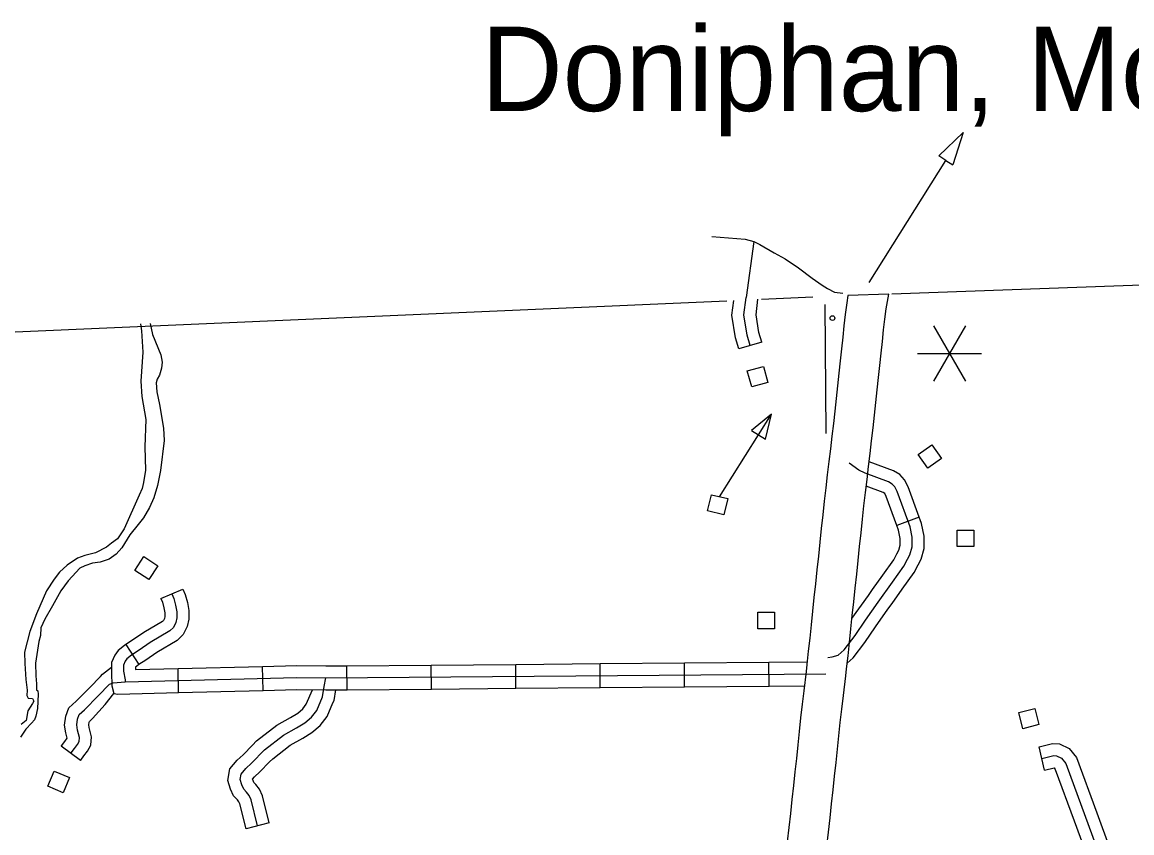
# Model space of a CAD drawing. Extents: x 1369885 to 1370219, y 379980 to 380218.
# Drawn here: x 1370027.37 to 1370054.99, y 380108.07 to 380128.26 of the extents above; entities that cross this region are included whole.
import ezdxf

# ---------------------------------------------------------------- set-up
doc = ezdxf.new("R2010")
doc.units = 0
for name, color, linetype in [('Default', 7, 'Continuous'), ('Level 1', 7, 'Continuous'), ('Level 10', 7, 'Continuous'), ('Level 24', 7, 'Continuous'), ('Level 32', 7, 'Continuous'), ('Level 35', 7, 'Continuous'), ('Level 45', 7, 'Continuous'), ('Level 48', 7, 'Continuous'), ('Level 5', 7, 'Continuous'), ('Level 56', 7, 'Continuous')]:
    doc.layers.add(name, color=color, linetype=linetype)

msp = doc.modelspace()

# ---------------------------------------------------------------- linework, layer by layer
at = {"layer": 'Default'}
for p, q in [((1370050.798, 380125.514), (1370050.187, 380124.926)), ((1370050.798, 380125.514), (1370050.536, 380124.707)), ((1370050.362, 380124.817), (1370050.187, 380124.926)), ((1370048.456, 380121.776), (1370050.362, 380124.817)), ((1370050.362, 380124.817), (1370050.536, 380124.707))]:
    msp.add_line(p, q, dxfattribs=at)
at = {"layer": 'Level 1'}
for points in [[(1370049.023, 380121.49), (1370068.595, 380122.2)], [(1370004.498, 380119.502), (1370026.044, 380120.496), (1370044.91, 380121.323)], [(1370045.775, 380121.361), (1370047.057, 380121.417)]]:
    msp.add_lwpolyline(points, dxfattribs=at)
at = {"layer": 'Level 10'}
for points in [[(1370048.943, 380121.487), (1370047.928, 380121.45), (1370047.897, 380121.272), (1370047.859, 380120.981), (1370047.828, 380120.697), (1370047.799, 380120.412), (1370047.768, 380120.123), (1370047.734, 380119.824), (1370047.701, 380119.515), (1370047.668, 380119.204), (1370047.634, 380118.89), (1370047.6, 380118.576), (1370047.566, 380118.264), (1370047.53, 380117.951), (1370047.492, 380117.635), (1370047.454, 380117.315), (1370047.415, 380116.99), (1370047.377, 380116.66), (1370047.34, 380116.327), (1370047.303, 380115.991), (1370047.266, 380115.649), (1370047.231, 380115.306), (1370047.194, 380114.964), (1370047.157, 380114.618), (1370047.12, 380114.274), (1370047.083, 380113.93), (1370047.047, 380113.589), (1370047.012, 380113.252), (1370046.978, 380112.921), (1370046.941, 380112.594), (1370046.904, 380112.265), (1370046.886, 380112.086), (1370046.831, 380111.608), (1370046.79, 380111.274), (1370046.749, 380110.934), (1370046.714, 380110.596), (1370046.679, 380110.262), (1370046.644, 380109.927), (1370046.609, 380109.59), (1370046.572, 380109.25), (1370046.533, 380108.906), (1370046.495, 380108.558), (1370046.454, 380108.209), (1370046.412, 380107.854)], [(1370047.4, 380107.737), (1370047.442, 380108.093), (1370047.483, 380108.446), (1370047.522, 380108.797), (1370047.56, 380109.142), (1370047.598, 380109.484), (1370047.633, 380109.823), (1370047.668, 380110.158), (1370047.703, 380110.492), (1370047.738, 380110.824), (1370047.777, 380111.156), (1370047.818, 380111.491), (1370047.874, 380111.978), (1370047.893, 380112.158), (1370047.93, 380112.484), (1370047.966, 380112.815), (1370048.001, 380113.149), (1370048.036, 380113.486), (1370048.072, 380113.826), (1370048.108, 380114.167), (1370048.146, 380114.512), (1370048.182, 380114.857), (1370048.22, 380115.202), (1370048.255, 380115.545), (1370048.291, 380115.883), (1370048.328, 380116.218), (1370048.365, 380116.548), (1370048.403, 380116.874), (1370048.442, 380117.197), (1370048.48, 380117.517), (1370048.518, 380117.836), (1370048.554, 380118.153), (1370048.589, 380118.469), (1370048.622, 380118.784), (1370048.656, 380119.099), (1370048.689, 380119.409), (1370048.722, 380119.713), (1370048.757, 380120.014), (1370048.788, 380120.31), (1370048.817, 380120.593), (1370048.847, 380120.862), (1370048.881, 380121.124), (1370048.943, 380121.487)]]:
    msp.add_lwpolyline(points, dxfattribs=at)
at = {"layer": 'Level 32'}
for p, q in [((1370030.823, 380113.911), (1370031.375, 380114.138)), ((1370029.954, 380112.761), (1370030.279, 380112.261)), ((1370031.268, 380111.567), (1370031.253, 380112.164)), ((1370033.368, 380111.619), (1370033.353, 380112.215)), ((1370035.463, 380111.637), (1370035.458, 380112.233)), ((1370037.563, 380111.654), (1370037.558, 380112.25)), ((1370039.663, 380111.671), (1370039.658, 380112.267)), ((1370041.763, 380111.688), (1370041.759, 380112.285)), ((1370043.864, 380111.705), (1370043.859, 380112.302)), ((1370045.964, 380111.722), (1370045.959, 380112.319))]:
    msp.add_line(p, q, dxfattribs=at)
for points in [[(1370044.54, 380122.921), (1370045.369, 380122.858), (1370045.586, 380122.794), (1370045.735, 380122.721), (1370046.092, 380122.517), (1370046.368, 380122.364), (1370046.696, 380122.139), (1370047.036, 380121.887), (1370047.287, 380121.709), (1370047.419, 380121.624), (1370047.597, 380121.539), (1370047.802, 380121.507)], [(1370031.375, 380114.138), (1370031.428, 380114.008), (1370031.485, 380113.805), (1370031.52, 380113.606), (1370031.524, 380113.392), (1370031.478, 380113.21), (1370031.383, 380113.01), (1370031.234, 380112.861), (1370030.724, 380112.561), (1370030.452, 380112.373), (1370030.279, 380112.261)], [(1370031.099, 380114.025), (1370031.146, 380113.911), (1370031.193, 380113.739), (1370031.222, 380113.577), (1370031.225, 380113.426), (1370031.196, 380113.311), (1370031.136, 380113.185), (1370031.05, 380113.099), (1370030.563, 380112.812), (1370030.286, 380112.621), (1370030.095, 380112.497), (1370029.981, 380112.406), (1370029.938, 380112.349), (1370029.895, 380112.249), (1370029.895, 380112.096), (1370029.933, 380111.885), (1370029.933, 380111.833)], [(1370030.823, 380113.911), (1370030.863, 380113.814), (1370030.902, 380113.673), (1370030.924, 380113.548), (1370030.926, 380113.46), (1370030.914, 380113.412), (1370030.889, 380113.36), (1370030.866, 380113.337), (1370030.403, 380113.064), (1370030.12, 380112.869), (1370029.954, 380112.761)], [(1370029.954, 380112.761), (1370029.921, 380112.74), (1370029.765, 380112.616), (1370029.677, 380112.499), (1370029.596, 380112.31), (1370029.596, 380112.069), (1370029.602, 380111.732), (1370029.654, 380111.543), (1370029.754, 380111.529), (1370031.268, 380111.567)], [(1370030.279, 380112.261), (1370030.27, 380112.255), (1370030.197, 380112.197), (1370030.193, 380112.187), (1370030.193, 380112.137), (1370031.253, 380112.164)], [(1370031.253, 380112.164), (1370033.353, 380112.215)], [(1370033.353, 380112.215), (1370034.209, 380112.236), (1370034.933, 380112.229), (1370035.458, 380112.233)], [(1370035.458, 380112.233), (1370037.558, 380112.25)], [(1370037.558, 380112.25), (1370039.658, 380112.267)], [(1370039.658, 380112.267), (1370041.759, 380112.285)], [(1370041.759, 380112.285), (1370043.859, 380112.302)], [(1370043.859, 380112.302), (1370045.959, 380112.319)], [(1370045.959, 380112.319), (1370046.911, 380112.327)], [(1370029.933, 380111.833), (1370034.211, 380111.938), (1370034.932, 380111.931), (1370047.38, 380112.032)], [(1370031.268, 380111.567), (1370033.368, 380111.619)], [(1370033.368, 380111.619), (1370034.213, 380111.639), (1370034.932, 380111.632), (1370035.463, 380111.637)], [(1370035.463, 380111.637), (1370037.563, 380111.654)], [(1370037.563, 380111.654), (1370039.663, 380111.671)], [(1370039.663, 380111.671), (1370041.763, 380111.688)], [(1370041.763, 380111.688), (1370043.864, 380111.705)], [(1370043.864, 380111.705), (1370045.964, 380111.722)], [(1370045.964, 380111.722), (1370046.845, 380111.729)]]:
    msp.add_lwpolyline(points, dxfattribs=at)
at = {"layer": 'Level 35'}
for points in [[(1370030.321, 380120.748), (1370030.346, 380120.575), (1370030.378, 380120.038), (1370030.328, 380119.323), (1370030.348, 380118.937), (1370030.449, 380118.363), (1370030.425, 380117.684), (1370030.443, 380117.102), (1370030.393, 380116.794), (1370030.358, 380116.643), (1370030.284, 380116.48), (1370029.909, 380115.645), (1370029.747, 380115.396), (1370029.599, 380115.286), (1370029.469, 380115.187), (1370029.202, 380115.047), (1370028.935, 380114.98), (1370028.753, 380114.914), (1370028.492, 380114.737), (1370028.306, 380114.561), (1370028.166, 380114.386), (1370027.981, 380114.098), (1370027.727, 380113.526), (1370027.564, 380113.087), (1370027.431, 380112.571), (1370027.436, 380112.29), (1370027.464, 380111.893), (1370027.498, 380111.626), (1370027.488, 380111.492), (1370027.521, 380111.425), (1370027.631, 380111.42), (1370027.66, 380111.354), (1370027.627, 380111.296), (1370027.517, 380111.107), (1370027.469, 380110.868), (1370027.352, 380110.768)], [(1370030.56, 380120.758), (1370030.619, 380120.484), (1370030.826, 380119.973), (1370030.859, 380119.792), (1370030.84, 380119.643), (1370030.792, 380119.467), (1370030.735, 380119.366), (1370030.706, 380119.276), (1370030.726, 380119.051), (1370030.788, 380118.736), (1370030.893, 380118.148), (1370030.91, 380117.842), (1370030.817, 380117.094), (1370030.741, 380116.725), (1370030.654, 380116.418), (1370030.544, 380116.174), (1370030.391, 380115.912), (1370030.262, 380115.754), (1370030.057, 380115.491), (1370029.856, 380115.167), (1370029.713, 380115.009), (1370029.541, 380114.89), (1370029.317, 380114.808), (1370029.126, 380114.785), (1370028.931, 380114.721), (1370028.806, 380114.66), (1370028.621, 380114.456), (1370028.517, 380114.349), (1370028.334, 380114.101), (1370028.127, 380113.724), (1370027.937, 380113.393), (1370027.837, 380113.181), (1370027.832, 380112.985), (1370027.789, 380112.834), (1370027.703, 380112.297), (1370027.717, 380111.979), (1370027.727, 380111.779), (1370027.732, 380111.635), (1370027.765, 380111.612), (1370027.775, 380111.526), (1370027.751, 380111.172), (1370027.714, 380110.977)], [(1370027.714, 380110.977), (1370027.679, 380110.887), (1370027.603, 380110.801), (1370027.464, 380110.658), (1370027.33, 380110.452)]]:
    msp.add_lwpolyline(points, dxfattribs=at)
at = {"layer": 'Level 45'}
for p, q in [((1370045.782, 380120.29), (1370045.209, 380120.122)), ((1370049.705, 380115.929), (1370049.144, 380115.727)), ((1370028.823, 380109.872), (1370028.345, 380110.23)), ((1370052.822, 380109.637), (1370052.687, 380110.218)), ((1370033.525, 380108.318), (1370032.945, 380108.175))]:
    msp.add_line(p, q, dxfattribs=at)
for points in [[(1370045.586, 380122.794), (1370045.393, 380121.405)], [(1370045.209, 380120.122), (1370045.128, 380120.398), (1370045.04, 380120.961), (1370045.084, 380121.33)], [(1370045.496, 380120.206), (1370045.42, 380120.463), (1370045.341, 380120.967), (1370045.393, 380121.405)], [(1370045.782, 380120.29), (1370045.712, 380120.528), (1370045.642, 380120.973), (1370045.688, 380121.357)], [(1370047.424, 380112.439), (1370047.537, 380112.451), (1370047.685, 380112.5), (1370047.838, 380112.633), (1370048.105, 380112.989), (1370048.366, 380113.369), (1370048.682, 380113.813), (1370049.037, 380114.317), (1370049.323, 380114.712), (1370049.412, 380114.885), (1370049.471, 380114.998), (1370049.525, 380115.194), (1370049.525, 380115.434), (1370049.474, 380115.691), (1370049.157, 380116.57), (1370049.094, 380116.692), (1370049.032, 380116.758), (1370048.935, 380116.815), (1370048.361, 380117.029), (1370048.196, 380117.107), (1370047.956, 380117.275)], [(1370049.705, 380115.929), (1370049.431, 380116.69), (1370049.34, 380116.866), (1370049.221, 380116.993), (1370049.064, 380117.085), (1370048.455, 380117.312)], [(1370049.144, 380115.727), (1370048.883, 380116.451), (1370048.848, 380116.518), (1370048.844, 380116.523), (1370048.807, 380116.544), (1370048.383, 380116.702)], [(1370048.54, 380114.13), (1370048.795, 380114.491), (1370049.068, 380114.869), (1370049.147, 380115.022), (1370049.192, 380115.108), (1370049.227, 380115.235), (1370049.227, 380115.404), (1370049.186, 380115.611), (1370049.144, 380115.727)], [(1370049.028, 380113.786), (1370049.28, 380114.144), (1370049.578, 380114.555), (1370049.677, 380114.748), (1370049.751, 380114.889), (1370049.823, 380115.154), (1370049.824, 380115.463), (1370049.762, 380115.771), (1370049.705, 380115.929)], [(1370048.028, 380113.409), (1370048.438, 380113.986), (1370048.54, 380114.13)], [(1370047.908, 380112.298), (1370048.058, 380112.429), (1370048.347, 380112.815), (1370048.611, 380113.198), (1370048.925, 380113.641), (1370049.028, 380113.786)], [(1370029.321, 380111.966), (1370029.374, 380112.022), (1370029.596, 380112.195)], [(1370028.345, 380110.23), (1370028.352, 380110.239), (1370028.434, 380110.349), (1370028.496, 380110.432), (1370028.462, 380110.565), (1370028.428, 380110.751), (1370028.457, 380110.974), (1370028.537, 380111.187), (1370028.714, 380111.351), (1370029.056, 380111.693), (1370029.321, 380111.967)], [(1370033.235, 380108.246), (1370033.075, 380108.893), (1370033.022, 380109.003), (1370032.96, 380109.085), (1370032.889, 380109.161), (1370032.841, 380109.271), (1370032.798, 380109.4), (1370032.822, 380109.534), (1370032.941, 380109.672), (1370033.084, 380109.804), (1370033.409, 380110.139), (1370033.877, 380110.502), (1370034.205, 380110.687), (1370034.412, 380110.812), (1370034.574, 380110.951), (1370034.705, 380111.122), (1370034.848, 380111.457), (1370034.894, 380111.716), (1370034.932, 380111.931)], [(1370028.584, 380110.051), (1370028.591, 380110.061), (1370028.672, 380110.17), (1370028.749, 380110.271), (1370028.792, 380110.347), (1370028.801, 380110.443), (1370028.753, 380110.629), (1370028.73, 380110.758), (1370028.749, 380110.902), (1370028.792, 380111.016), (1370028.921, 380111.136), (1370029.269, 380111.484), (1370029.546, 380111.771), (1370029.637, 380111.809), (1370029.737, 380111.814), (1370029.933, 380111.833)], [(1370033.104, 380110.253), (1370033.21, 380110.362), (1370033.711, 380110.751), (1370034.055, 380110.945), (1370034.237, 380111.055), (1370034.356, 380111.157), (1370034.445, 380111.274), (1370034.6, 380111.636)], [(1370035.109, 380111.308), (1370035.136, 380111.371), (1370035.183, 380111.634)], [(1370028.823, 380109.872), (1370028.83, 380109.882), (1370028.911, 380109.991), (1370028.999, 380110.107), (1370029.082, 380110.255), (1370029.103, 380110.466), (1370029.045, 380110.693), (1370029.032, 380110.766), (1370029.04, 380110.829), (1370029.046, 380110.845), (1370029.127, 380110.921), (1370029.442, 380111.269), (1370029.654, 380111.543)], [(1370033.532, 380109.837), (1370033.609, 380109.916), (1370034.043, 380110.253), (1370034.356, 380110.43), (1370034.587, 380110.57), (1370034.792, 380110.745), (1370034.965, 380110.971), (1370035.109, 380111.308)], [(1370032.945, 380108.175), (1370032.793, 380108.792), (1370032.766, 380108.847), (1370032.732, 380108.892), (1370032.636, 380108.995), (1370032.562, 380109.164), (1370032.491, 380109.378), (1370032.542, 380109.667), (1370032.726, 380109.88), (1370032.876, 380110.018), (1370033.104, 380110.253)], [(1370052.687, 380110.218), (1370053.019, 380110.295), (1370053.193, 380110.291), (1370053.438, 380110.173), (1370053.618, 380109.945), (1370054.12, 380108.574)], [(1370052.754, 380109.927), (1370053.05, 380109.996), (1370053.121, 380109.994), (1370053.246, 380109.934), (1370053.354, 380109.798), (1370054.57, 380106.474)], [(1370033.525, 380108.318), (1370033.357, 380108.995), (1370033.278, 380109.16), (1370033.188, 380109.278), (1370033.142, 380109.327), (1370033.12, 380109.378), (1370033.109, 380109.41), (1370033.156, 380109.465), (1370033.293, 380109.59), (1370033.532, 380109.837)], [(1370052.822, 380109.637), (1370053.058, 380109.691), (1370053.09, 380109.651), (1370053.559, 380108.369)], [(1370054.12, 380108.574), (1370054.771, 380106.792)], [(1370053.559, 380108.369), (1370054.13, 380106.808)]]:
    msp.add_lwpolyline(points, dxfattribs=at)
at = {"layer": 'Level 48'}
for p, q in [((1370050.852, 380120.697), (1370050.056, 380119.319)), ((1370050.056, 380120.697), (1370050.852, 380119.319)), ((1370049.658, 380120.008), (1370051.249, 380120.008))]:
    msp.add_line(p, q, dxfattribs=at)
at = {"layer": 'Level 5'}
msp.add_lwpolyline([(1370047.352, 380121.227), (1370047.381, 380118.019)], dxfattribs=at)
at = {"layer": 'Level 56'}
for points in [[(1370045.535, 380119.177), (1370045.423, 380119.575), (1370045.823, 380119.687), (1370045.934, 380119.288)], [(1370045.529, 380118.09), (1370045.873, 380117.875), (1370046.025, 380118.498)], [(1370049.916, 380117.156), (1370049.679, 380117.495), (1370050.019, 380117.733), (1370050.256, 380117.394)], [(1370044.435, 380116.088), (1370044.531, 380116.491), (1370044.935, 380116.394), (1370044.839, 380115.991)], [(1370050.646, 380115.199), (1370050.646, 380115.613), (1370051.062, 380115.613), (1370051.062, 380115.199)], [(1370030.18, 380114.604), (1370030.405, 380114.951), (1370030.754, 380114.725), (1370030.528, 380114.378)], [(1370045.683, 380113.156), (1370045.683, 380113.57), (1370046.098, 380113.57), (1370046.098, 380113.156)], [(1370052.28, 380110.666), (1370052.179, 380111.068), (1370052.582, 380111.168), (1370052.682, 380110.767)], [(1370028.008, 380109.231), (1370028.171, 380109.612), (1370028.553, 380109.449), (1370028.39, 380109.068)]]:
    msp.add_lwpolyline(points, close=True, dxfattribs=at)
msp.add_lwpolyline([(1370044.733, 380116.442), (1370046.025, 380118.498)], dxfattribs=at)
msp.add_circle((1370047.542, 380120.889), 0.0597, dxfattribs=at)

# ---------------------------------------------------------------- texts
at = {"layer": 'Level 24'}
msp.add_text('Doniphan, Mo', height=2.10029, dxfattribs=at).set_placement((1370038.8, 380126.045))

doc.saveas('drawing.dxf')
